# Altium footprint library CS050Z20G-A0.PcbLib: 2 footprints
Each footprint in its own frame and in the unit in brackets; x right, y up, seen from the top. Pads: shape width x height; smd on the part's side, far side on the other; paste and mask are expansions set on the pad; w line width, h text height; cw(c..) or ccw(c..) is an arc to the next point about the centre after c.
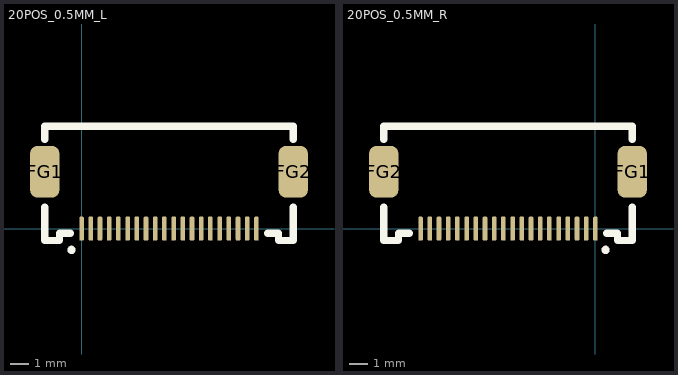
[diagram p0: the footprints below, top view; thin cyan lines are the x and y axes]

## 20POS_0.5MM_L [mm] "8pin .05mm pitch connector"
pads (22):
  rrect50% 0.25x1.3 smd mask+0.05: 1(0,0) 2(0.5,0) 3(1,0) 4(1.5,0) 5(2,0) 6(2.5,0) 7(3,0) 8(3.5,0) 9(4,0) 10(4.5,0) 11(5,0) 12(5.5,0) 13(6,0) 14(6.5,0) 15(7,0) 16(7.5,0) 17(8,0) 18(8.5,0) 19(9,0) 20(9.5,0)
  rrect50% 1.6x2.8 smd: FG1(-2,3.09) FG2(11.5,3.09)
Top Overlay:
  circle w0.254: c-0.55,-1.155 r0.1
  lines w0.4: -2,1.155 -2,-0.645 -1.2,-0.645 -1.2,-0.245 -0.6,-0.245 ; -2,4.86 -2,5.56 ; -1.95,5.56 11.5,5.56 11.5,4.86 ; 10.1,-0.245 10.7,-0.245 10.7,-0.645 11.5,-0.645 11.5,1.155

## 20POS_0.5MM_R [mm]
pads (22):
  rrect50% 0.25x1.3 smd mask+0.05: 1(0,0) 2(-0.5,0) 3(-1,0) 4(-1.5,0) 5(-2,0) 6(-2.5,0) 7(-3,0) 8(-3.5,0) 9(-4,0) 10(-4.5,0) 11(-5,0) 12(-5.5,0) 13(-6,0) 14(-6.5,0) 15(-7,0) 16(-7.5,0) 17(-8,0) 18(-8.5,0) 19(-9,0) 20(-9.5,0)
  rrect50% 1.6x2.8 smd: FG1(2,3.09) FG2(-11.5,3.09)
Top Overlay:
  circle w0.254: c0.55,-1.155 r0.1
  lines w0.4: -11.5,1.155 -11.5,-0.645 -10.7,-0.645 -10.7,-0.245 -10.1,-0.245 ; -11.5,4.86 -11.5,5.56 1.95,5.56 ; 0.6,-0.245 1.2,-0.245 1.2,-0.645 2,-0.645 2,1.155 ; 2,4.86 2,5.56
